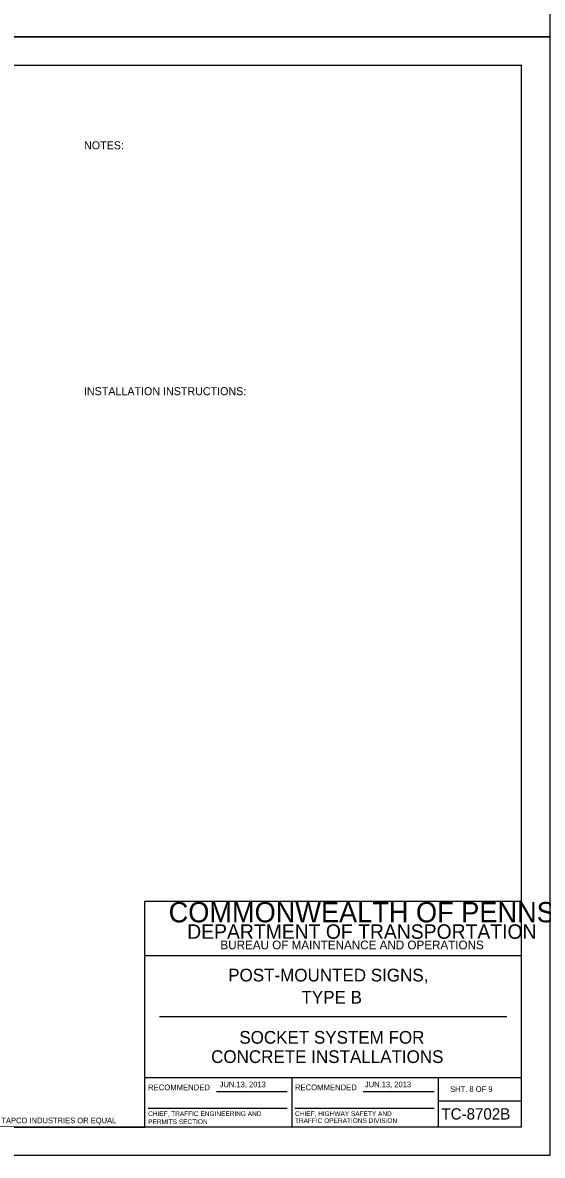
# Model space of a CAD drawing. Extents: x 644358 to 648627, y 294594 to 295782.
# Drawn here: x 646601 to 646877, y 294594 to 295195 of the extents above; entities that cross this region are included whole.
import ezdxf

# ---------------------------------------------------------------- set-up
doc = ezdxf.new("R2010")
doc.units = 0
for name, color, linetype in [('1', 7, 'Continuous'), ('2', 7, 'Continuous'), ('4', 7, 'Continuous'), ('PLT-BNDY', 7, 'Continuous')]:
    doc.layers.add(name, color=color, linetype=linetype)

msp = doc.modelspace()

# ---------------------------------------------------------------- linework, layer by layer
at = {"layer": '1'}
for p, q in [((646080.31, 295172.63), (646866.31, 295172.63)), ((646866.31, 294608.63), (646866.31, 295172.63)), ((646666.31, 294608.63), (646666.31, 294728.63)), ((646666.31, 294728.63), (646866.31, 294728.63)), ((646866.31, 294699.63), (646666.31, 294699.63)), ((646674.06, 294667.31), (646858.56, 294667.31)), ((646666.31, 294635), (646866.31, 294635)), ((646744.31, 294635), (646744.31, 294608.63)), ((646822.19, 294608.63), (646822.19, 294635)), ((646704.24, 294627.57), (646741.87, 294627.57)), ((646782.24, 294627.57), (646819.87, 294627.57)), ((646822.19, 294622.63), (646866.31, 294622.63)), ((646667.99, 294618.68), (646741.87, 294618.68)), ((646745.99, 294618.68), (646819.87, 294618.68)), ((646866.31, 294608.63), (646080.31, 294608.63)), ((646080.31, 294608.63), (646666.31, 294608.63))]:
    msp.add_line(p, q, dxfattribs=at)
at = {"layer": 'PLT-BNDY'}
for points in [[(646040.31, 295781.63), (646881.31, 295781.63), (646881.31, 295187.63), (646040.31, 295187.63)], [(646040.31, 295187.63), (646881.31, 295187.63), (646881.31, 294593.63), (646040.31, 294593.63)]]:
    msp.add_lwpolyline(points, close=True, dxfattribs=at)

# ---------------------------------------------------------------- texts
at = {"layer": '1'}
for s, height, p in [('COMMONWEALTH OF PENNSYLVANIA', 10.7828, (646678.9, 294717.36)), ('DEPARTMENT OF TRANSPORTATION', 7.6837, (646688.76, 294708.61)), ('BUREAU OF MAINTENANCE AND OPERATIONS', 4.6253, (646706.41, 294703.04)), ('POST-MOUNTED SIGNS,', 6.75, (646710.54, 294685.97)), ('TYPE B', 6.75, (646749.45, 294674.22)), ('SOCKET SYSTEM FOR', 6.75, (646716.45, 294652.91)), ('CONCRETE INSTALLATIONS', 6.75, (646701.47, 294642.66)), ('RECOMMENDED', 3.048, (646667.99, 294628.2)), ('RECOMMENDED', 3.048, (646745.99, 294628.2)), ('SHT. 8 OF 9', 3, (646828.39, 294627.31)), ('CHIEF, TRAFFIC ENGINEERING AND', 2.5, (646667.99, 294614.51)), ('CHIEF, HIGHWAY SAFETY AND', 2.5, (646745.99, 294614.51)), ('TC-8702B', 6, (646823.77, 294612.63)), ('PERMITS SECTION', 2.5, (646667.99, 294610.26)), ('TRAFFIC OPERATIONS DIVISION', 2.5, (646745.99, 294610.81))]:
    msp.add_text(s, height=height, dxfattribs=at).set_placement(p)
at = {"layer": '2'}
for s, p in [('JUN.13, 2013', (646705.98, 294629.79)), ('JUN.13, 2013', (646783.14, 294629.79)), ('TAPCO INDUSTRIES OR EQUAL', (646590.05, 294610.66))]:
    msp.add_text(s, height=3, dxfattribs=at).set_placement(p)
at = {"layer": '4'}
for s, p in [('NOTES:', (646633.97, 295127.87)), ('INSTALLATION INSTRUCTIONS:', (646633.91, 294997.29))]:
    msp.add_text(s, height=4.25, dxfattribs=at).set_placement(p)

doc.saveas('drawing.dxf')
